// Mitsubishi GX Works2 project: 并联电路例程   PLC: FX1S

PROGRAM MAIN
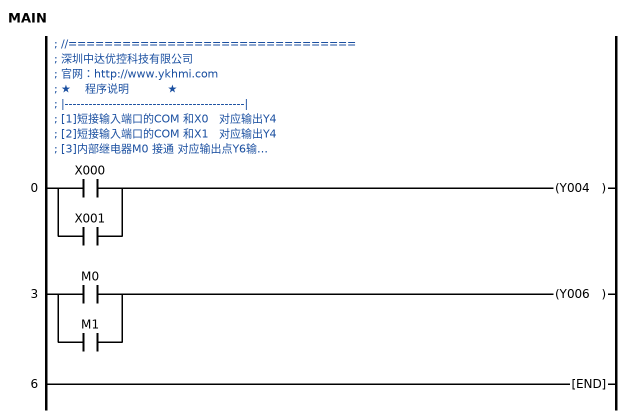
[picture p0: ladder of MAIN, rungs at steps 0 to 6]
; //================================
; 深圳中达优控科技有限公司
; 官网：http://www.ykhmi.com
; ★    程序说明           ★
; |---------------------------------------------|
; [1]短接输入端口的COM 和X0   对应输出Y4
; [2]短接输入端口的COM 和X1   对应输出Y4
; [3]内部继电器M0 接通 对应输出点Y6输出
; [4]内部继电器M1 接通 对应输出点Y6输出
; 
0     LD      X000
      OR      X001
      OUT     Y004
3     LD      M0
      OR      M1
      OUT     Y006
6     END
END_PROGRAM
